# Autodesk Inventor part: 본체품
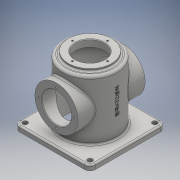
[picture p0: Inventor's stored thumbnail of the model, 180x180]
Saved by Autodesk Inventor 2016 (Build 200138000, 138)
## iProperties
Created: 2019-08
Part Number: 본체품
Material: 일반
Document SubType Name: Modeling
Designer: user
Density: 1 g/cm^3
Appearance: 기본값
Author: user
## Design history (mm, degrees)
node "작업 평면2"
sketch "스케치3"
  geometry: L1 (-70, 70)-(70, 70); L2 (70, 70)-(70, -70); L3 (70, -70)-(-70, -70); L4 (-70, -70)-(-70, 70); L5 (-70, 70)-(70, -70); L6 (70, 70)-(-70, -70); 1 further point
  constraints: 12 end point, 2 midpoint, 2 parallel, 1 horizontal, 1 perpendicular
  dimensions: "d8" = 140 distance of L1.start L1.end; "d9" = 140 distance of L1.end L2.end
extrude "돌출2" new body sketch "스케치3" distance "d10" = 10; taper "d11" = 0 deg
fillet "모깎기2" dims "d12" = 10
sketch "스케치4"
  geometry: C1 r 50 at (0, 0); 1 further point
  constraints: 1 centre point, 1 coincident
  dimensions: "d13" = 100 diameter of C1
extrude "돌출3" join sketch "스케치4" distance "d14" = 110; taper "d15" = 0 deg
sketch "스케치8"
  geometry: C1 r 40 at (0, 0); 1 further point
  constraints: 1 centre point, 1 coincident
  dimensions: "d42" = 80 diameter of C1
extrude "돌출6" join sketch "스케치8" stored distance "d43" = 124; taper "d44" = 0 deg
sketch "스케치5"
  geometry: C1 r 40 at (0, 0); 1 further point
  constraints: 1 centre point, 1 coincident
  dimensions: "d16" = 80 diameter of C1
extrude "돌출4" join sketch "스케치5" distance "d17" = 5; taper "d18" = 0 deg
sketch "스케치6"
  geometry: C1 r 45 at (0, 0); 1 further point
  constraints: 1 centre point, 1 coincident
  dimensions: "d19" = 90 diameter of C1
extrude "돌출5" cut sketch "스케치6" distance "d20" = 112; taper "d21" = 0 deg
hole "구멍1" diameter "d24" = 54; stored, may be unused: countersink angle "d28" = 90 deg, drill point angle "d30" = 118 deg; dims "d22" = 10, "d23" = 10, "d25" = 6, "d26" = 4, "d27" = 2, "d29" = 8
sketch "스케치7" dims "d31" = 65
  geometry: 3 further points
  constraints: 2 horizontal alignment, 1 coincident, 2 other
hole "구멍2" sketch "스케치7" at (32.5, 0) diameter "d32" = 3.242; stored, may be unused: countersink angle "d36" = 90 deg, drill point angle "d38" = 118 deg; dims "d33" = 8, "d34" = 4, "d35" = 2, "d37" = 10
sketch "스케치9"
  geometry: C1 r 27 at (0, 0); 1 further point
  constraints: 1 centre point, 1 coincident
  dimensions: "d45" = 54 diameter of C1
extrude "돌출7" cut sketch "스케치9" stored distance "d46" = 124; taper "d47" = 0 deg
sketch "스케치10" dims "d48" = 65
  geometry: 3 further points
  constraints: 2 horizontal alignment, 1 coincident, 2 other
hole "구멍3" sketch "스케치10" at (32.5, 0) diameter "d49" = 3.242; stored, may be unused: countersink angle "d53" = 90 deg, drill point angle "d55" = 118 deg; dims "d50" = 8, "d51" = 4, "d52" = 2, "d54" = 10
hole "구멍4" diameter "d64" = 9; stored, may be unused: countersink angle "d68" = 90 deg, drill point angle "d70" = 118 deg; dims "d65" = 9, "d66" = 4, "d67" = 2, "d69" = 9, "d71" = 10, "d72" = 10
hole "구멍5" diameter "d75" = 9; stored, may be unused: countersink angle "d79" = 90 deg, drill point angle "d81" = 118 deg; dims "d73" = 10, "d74" = 10, "d76" = 6, "d77" = 4, "d78" = 2, "d80" = 8
fillet "모깎기3" dims "d82" = 5
fillet "모깎기4" dims "d83" = 3
fillet "모깎기5" dims "d84" = 3
fillet "모깎기6" dims "d85" = 3
fillet "모깎기7" dims "d86" = 3
chamfer "모따기1" distance "d87" = 1; stored, may be unused: second distance "d88" = 2, angle "d89" = 45 deg
chamfer "모따기2" distance "d90" = 1; stored, may be unused: second distance "d91" = 2, angle "d92" = 45 deg
chamfer "모따기3" distance "d93" = 1; stored, may be unused: second distance "d94" = 2, angle "d95" = 45 deg
fillet "모깎기8" dims "d96" = 3
node "작업 평면3"
sketch "스케치11"
  geometry: L1 (60, -65)-(-60, -65) reference; 2 further points
  constraints: 1 vertical alignment, 1 other
  dimensions: "d98" = 70 distance from line of L1 point (0, 5)
feature "엠보싱1" sketch "스케치11" dims "d16" = 80, "d99" = 0.5, "d100" = 0
node "솔리드2"
pattern_circular "원형 패턴1" dims angle "d40" = 360 deg
pattern_circular "원형 패턴2" dims angle "d57" = 360 deg
mirror "대칭1"
pattern_circular "원형 패턴3" dims angle "d60" = 360 deg
mirror "대칭2"
other parameters: "d7" = -65
